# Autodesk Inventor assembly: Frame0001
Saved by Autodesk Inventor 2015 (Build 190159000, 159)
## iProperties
Created: 2020-03
Part Number: Frame0001
Document SubType Name: Assembly
Designer: 徐冠倫
_FrameDoc: Frame Assembly
_Version: 15.0.0
Author: 徐冠倫
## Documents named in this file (4)
- C:\Users\徐冠倫\Desktop\Topic 13-3_框架分析(銷約束)\Topic 13-3_框架分析(銷約束)\Frame\Frame0001.iam
- C:\Users\徐冠倫\Desktop\Topic 13-3_框架分析(銷約束)\Topic 13-3_框架分析(銷約束)\Frame\Skeleton0001.ipt
- C:\Users\徐冠倫\Desktop\Topic 13-3_框架分析(銷約束)\Topic 13-3_框架分析(銷約束)\Frame\ISO 30x30x3 00000001.ipt
- ISO 30x30x3 00000001.ipt
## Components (2 placed, 2 different names)
1. Frame Reference Model
2. ISO 30x30x3 00000001:1
